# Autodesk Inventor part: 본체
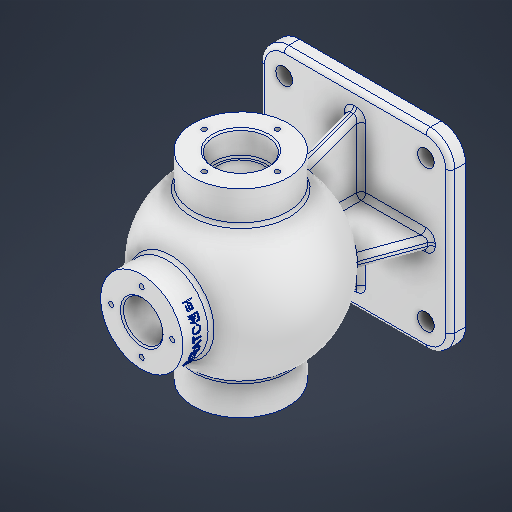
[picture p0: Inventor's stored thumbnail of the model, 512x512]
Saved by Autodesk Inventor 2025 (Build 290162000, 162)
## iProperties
Created: 2025-08
Part Number: 본체
Material: 알루미늄 6061
Document SubType Name: Modeling
Designer: infra10
Density: 2.7 g/cm^3
Appearance: 알루미늄 - 평지
Mass: 1525.62 g
Surface Area: 1200.53 cm^2
Volume: 565.046 cm^3
Author: infra10
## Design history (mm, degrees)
sketch "스케치1"
  geometry: L1 (-62.5, -62.5)-(62.5, -62.5); L2 (62.5, -62.5)-(62.5, 62.5); L3 (62.5, 62.5)-(-62.5, 62.5); L4 (-62.5, 62.5)-(-62.5, -62.5); L5 (-62.5, -62.5)-(62.5, 62.5); L6 (62.5, -62.5)-(-62.5, 62.5); 1 further point
  constraints: 12 end point, 2 midpoint, 2 parallel, 1 horizontal, 1 perpendicular
  dimensions: "d0" = 125 distance of L3.end L2.end; "d1" = 125 distance of L2.end L1.end
extrude "돌출1" new body sketch "스케치1" distance "d2" = 10; taper "d3" = 0 deg
node "작업 평면1"
sketch "스케치2"
  geometry: L1 (62.5, -62.5)-(-62.5, -62.5) reference; L2 (0, 0)-(0, 54); L3 (0, 54)-(0, -54); A1 r 54 centre (0, 0) between (0, -54) and (0, 54); A2 r 44 centre (0, 0) between (0, -44) and (0, 44); 3 further points
  constraints: 4 end point, 4 point on circle, 3 point on line, 2 centre point, 2 coincident, 1 midpoint, 1 vertical
  dimensions: "d5" = 108 diameter of A1; "d7" = 88 diameter of A2
revolve "회전1" sketch "스케치2" stored, may be unused: angle "d6" = 360 deg
node "작업 평면2"
sketch "스케치4"
  geometry: C1 r 54 at (0, 85) reference; C2 r 31 at (0, 85); 1 further point
  constraints: 1 centre point, 1 coincident
  dimensions: "d9" = 62 diameter of C2
extrude "돌출2" join sketch "스케치4" stored distance "d10" = 10; taper "d11" = 0 deg
node "작업 평면3"
sketch "스케치5"
  geometry: C1 r 31 at (0, 85) reference; 1 further point
extrude "돌출3" join sketch "스케치5" stored distance "d13" = 10; taper "d14" = 0 deg
sketch "스케치6"
  geometry: L1 (62.5, 0)-(62.5, 10) reference; L2 (62.5, 10)-(50.5, 10); L3 (-62.5, 10)-(62.5, 10) reference; L4 (50.5, 10)-(37.385, 46.034); L5 (-62.5, 10)-(-50.5, 10); L6 (-50.5, 10)-(-37.385, 46.034); A1 r 54 centre (0, 85) between (44.215, 116) and (44.215, 54) reference; 1 further point
  constraints: 8 end point, 2 point on circle, 2 point on line
  dimensions: "d15" = 12 distance of L1.end L2.end; "d16" = 110 deg angle of L2 L4; "d17" = 12 distance of L3.start L5.end; "d18" = 110 deg angle of L6 L5
extrude "돌출4" join sketch "스케치6" stored distance "d19" = 8; taper "d20" = 0 deg
sketch "스케치7"
  geometry: L1 (-62.5, 10)-(-50.5, 10); L2 (-62.5, 10)-(62.5, 10) reference; L3 (-50.5, 10)-(-37.385, 46.034); L4 (62.5, 10)-(50.5, 10); L5 (62.5, 0)-(62.5, 10) reference; L6 (62.5, 10)-(50.5, 10); L7 (50.5, 10)-(37.385, 46.034); 4 further points
  constraints: 10 end point, 2 point on line, 1 collinear, 4 other
  dimensions: "d21" = 12 distance of L1.start L1.end; "d22" = 110 deg angle of L3 L1; "d24" = 12 distance of L2.end L4.end; "d25" = 110 deg angle of L6 L7
extrude "돌출5" join sketch "스케치7" stored distance "d26" = 8; taper "d27" = 0 deg
node "작업 평면4"
sketch "스케치8"
  geometry: L1 (0, -37.385)-(0, 0) reference; C1 r 27 at (0, 0)
  constraints: 1 centre point, 1 coincident
  dimensions: "d29" = 54 diameter of C1
extrude "돌출6" join sketch "스케치8" stored distance "d30" = 8; taper "d31" = 0 deg
sketch "스케치9"
  geometry: C1 r 31 at (0, 0) reference; 2 further points
  constraints: 1 coincident
hole "구멍1" sketch "스케치9" at (0, 0) diameter "d32" = 30; stored, may be unused: countersink angle "d36" = 90 deg, drill point angle "d38" = 118 deg; dims "d33" = 6, "d34" = 35, "d35" = 16, "d37" = 30
sketch "스케치10"
  geometry: C1 r 31 at (0, 0) reference; 2 further points
  constraints: 1 coincident
hole "구멍2" sketch "스케치10" at (0, 0) diameter "d39" = 30; stored, may be unused: countersink angle "d43" = 90 deg, drill point angle "d45" = 118 deg; dims "d40" = 6, "d41" = 35, "d42" = 16, "d44" = 30
sketch "스케치11"
  geometry: 2 further points
  constraints: 1 coincident
hole "구멍3" sketch "스케치11" at (0, 0) diameter "d46" = 26; stored, may be unused: countersink angle "d50" = 90 deg, drill point angle "d52" = 118 deg; dims "d47" = 6, "d48" = 35, "d49" = 16, "d51" = 40
sketch "스케치12"
  geometry: L1 (46.5, 46.5)-(-46.5, 46.5); L2 (-46.5, 46.5)-(-46.5, -46.5); L3 (-46.5, -46.5)-(46.5, -46.5); L4 (46.5, -46.5)-(46.5, 46.5); L5 (46.5, 46.5)-(-46.5, -46.5); L6 (-46.5, 46.5)-(46.5, -46.5); 1 further point
  constraints: 12 end point, 2 midpoint, 2 parallel, 1 horizontal, 1 perpendicular
  dimensions: "d53" = 93 distance of L3.end L2.end; "d54" = 93 distance of L2.end L1.end
hole "구멍4" sketch "스케치12" at (46.5, -46.5), (46.5, 46.5), (-46.5, 46.5), (-46.5, -46.5) diameter "d55" = 11; stored, may be unused: countersink angle "d59" = 90 deg, drill point angle "d61" = 118 deg; dims "d56" = 6, "d57" = 4, "d58" = 2, "d60" = 40
sketch "스케치13"
  geometry: L1 (0, 0)-(0, -24); L2 (0, 0)-(-24, 0); L3 (0, 0)-(0, 24); L4 (0, 0)-(24, 0); C1 r 31 at (0, 0) reference; A1 r 24 centre (0, 0) between (0, -24) and (-24, 0); 1 further point
  constraints: 8 end point, 4 point on circle, 2 point on line, 1 centre point, 1 coincident, 1 perpendicular, 1 vertical
  dimensions: "d63" = 48 diameter of A1
hole "구멍5" sketch "스케치13" at (0, -24), (24, 0), (0, 24), (-24, 0) diameter "d64" = 3.242; stored, may be unused: countersink angle "d68" = 90 deg, drill point angle "d70" = 118 deg; dims "d65" = 12, "d66" = 4, "d67" = 2, "d69" = 15
sketch "스케치14"
  geometry: C1 r 1.621 at (-24, 0) reference; C2 r 1.621 at (0, 24) reference; C3 r 1.621 at (0, -24) reference; C4 r 1.621 at (24, 0) reference; 1 further point
hole "구멍6" sketch "스케치14" at (0, 24), (-24, 0), (0, -24), (24, 0) diameter "d71" = 3.242; stored, may be unused: countersink angle "d75" = 90 deg, drill point angle "d77" = 118 deg; dims "d72" = 12, "d73" = 4, "d74" = 2, "d76" = 15
sketch "스케치15"
  geometry: L1 (0, 0)-(-4, -4) reference; L2 (0, 0)-(-37.385, 0) reference; L3 (0, 0)-(0, 20); L4 (0, 0)-(0, 37.385) reference; L5 (0, 0)-(-20, 0); L6 (0, 0)-(20, 0); L7 (0, 0)-(0, -20); A1 r 20 centre (0, 0) between (0, 20) and (-20, 0)
  constraints: 8 end point, 4 point on circle, 3 point on line, 1 centre point, 1 coincident, 1 perpendicular
  dimensions: "d78" = 40 diameter of A1
hole "구멍7" sketch "스케치15" at (0, 20), (-20, 0), (0, -20), (20, 0) diameter "d79" = 3.242; stored, may be unused: countersink angle "d83" = 90 deg, drill point angle "d85" = 118 deg; dims "d80" = 9, "d81" = 4, "d82" = 2, "d84" = 11
node "작업 평면5"
sketch "스케치16"
  geometry: L1 (-12.632, 144.777)-(12.632, 144.777); L2 (12.632, 144.777)-(12.632, 137.223); L3 (12.632, 137.223)-(-12.632, 137.223); L4 (-12.632, 137.223)-(-12.632, 144.777); L5 (27, 150)-(-27, 150) reference; L6 (65, 54)-(65, 116) reference; L7 (-65, 54)-(-65, 116) reference; 4 further points
  constraints: 3 midpoint, 1 parallel, 2 other
  dimensions: "d89" = 9 distance from line of L5 point (-12.632, 141); "d90" = 65 distance from line of L7 point (0, 144.777); "d91" = 52.36799 distance between parallel lines of L7 L4; "d92" = 5.22342 distance between parallel lines of L1 L5
feature "엠보싱1" sketch "스케치16" dims "d93" = 0.5, "d94" = 0
fillet "모깎기1" dims "d95" = 16
fillet "모깎기2" dims "d96" = 3
fillet "모깎기3" dims "d97" = 3
fillet "모깎기4" dims "d98" = 3
fillet "모깎기5" dims "d99" = 3
fillet "모깎기6" dims "d100" = 3
chamfer "모따기1" distance "d101" = 1; stored, may be unused: second distance "d102" = 2, angle "d103" = 45 deg
chamfer "모따기2" distance "d104" = 1; stored, may be unused: second distance "d105" = 2, angle "d106" = 45 deg
chamfer "모따기3" distance "d107" = 1; stored, may be unused: second distance "d108" = 2, angle "d109" = 45 deg
chamfer "모따기4" distance "d110" = 1; stored, may be unused: second distance "d111" = 2, angle "d112" = 45 deg
chamfer "모따기5" distance "d113" = 1; stored, may be unused: second distance "d114" = 2, angle "d115" = 45 deg
feature "С耀У耀Х耀Ч耀Щ耀Ы耀Э耀Я耀" dims "d0" = 125, "d1" = 125, "d2" = 10, "d3" = 0, "d4" = -85, "d5" = 108, "d6" = 360 deg, "d7" = 88, "d8" = 65, "d9" = 62, "d10" = 10, "d11" = 0, "d12" = -65, "d13" = 10, "d14" = 0, "d15" = 12, "d16" = 110 deg, "d17" = 12, "d18" = 110 deg, "d19" = 8, "d20" = 0, "d21" = 12, "d22" = 110 deg, "d24" = 12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
node "솔리드1"
feature "A9D066F2-1C7D-4E18-AEED-F7BC21143FA4" dims "d32" = 30, "d33" = 6, "d34" = 35, "d35" = 16, "d36" = 90 deg, "d37" = 30, "d38" = 118 deg
